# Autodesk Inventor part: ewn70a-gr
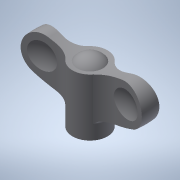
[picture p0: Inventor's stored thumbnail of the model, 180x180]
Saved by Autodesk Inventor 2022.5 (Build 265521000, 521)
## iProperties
Created: 2016-12
Part Number: ewn70a-gr
Material: 一般
Document SubType Name: Modeling
Designer: imaocorp
Density: 1 g/cm^3
Appearance: 既定
Author: imaocorp
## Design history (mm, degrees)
node "ewn70a-gr.x_t1"
node "ewn70a-gr"
node "Base1"
